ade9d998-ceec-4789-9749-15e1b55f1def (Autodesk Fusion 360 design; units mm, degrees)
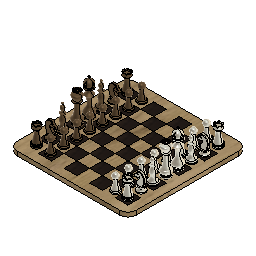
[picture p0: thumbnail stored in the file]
sketch "Sketch1" plane through (0, 0, 0) normal (0, 0, 1) x axis (1, 0, 0)
  line L1 (280, 0) -> (0, 0)
  line L2 (280, 280) -> (280, 0)
  line L3 (0, 280) -> (280, 280)
  line L4 (0, 0) -> (0, 280)
  point P1 (0, 0)
  point P2 (0, 0)
  point P3 (280, 0)
  point P5 (0, 280)
  horizontal L1
  vertical L2
  horizontal L3
  vertical L4
  coincident P1 P2
  dimension "d1" distance P2 P3 = 280
  dimension "d2" distance P2 P5 = 280
extrude "Extrude1" new body sketch "Sketch1" along normal blind 10
sketch "Sketch2" plane through (0, 0, 10) normal (0, 0, 1) x axis (-1, 0, 0)
  line L1 (0, 0) -> (0, -280)
  line L2 (-280, 0) -> (0, 0)
  line L3 (-280, -280) -> (-280, 0)
  line L4 (0, -280) -> (-280, -280)
  line L5 (-50, -260) -> (-20, -260)
  line L6 (-50, -230) -> (-50, -260)
  line L7 (-20, -230) -> (-50, -230)
  line L8 (-20, -260) -> (-20, -230)
  point P6 (-20, -260)
  point P7 (-50, -260)
  point P9 (-20, -230)
  point P2 (0, -280)
  horizontal L5
  vertical L6
  horizontal L7
  vertical L8
  dimension "d5" distance P6 P7 = 30
  dimension "d6" distance P6 P9 = 30
  dimension "d7" distance P2 P6 = 20
  dimension "d8" distance L4 L5 = 20
extrude "Extrude2" cut sketch "Sketch2" profile of L5 L6 L7 L8 against normal blind 10
rectangular_pattern "R-Pattern1" uSpaceDistance -60 vSpaceDistance -60
sketch "Sketch3" plane through (0, 0, 10) normal (0, 0, 1) x axis (-1, 0, 0)
  line L1 (-230, -50) -> (-230, -80)
  line L2 (-200, -50) -> (-230, -50)
  line L3 (-200, -80) -> (-200, -50)
  line L4 (-230, -80) -> (-200, -80)
  line L5 (-170, -50) -> (-170, -80)
  line L6 (-140, -50) -> (-170, -50)
  line L7 (-140, -80) -> (-140, -50)
  line L8 (-170, -80) -> (-140, -80)
  line L9 (-110, -50) -> (-110, -80)
  line L10 (-80, -50) -> (-110, -50)
  line L11 (-80, -80) -> (-80, -50)
  line L12 (-110, -80) -> (-80, -80)
  line L13 (-50, -50) -> (-50, -80)
  line L14 (-20, -50) -> (-50, -50)
  line L15 (-20, -80) -> (-20, -50)
  line L16 (-50, -80) -> (-20, -80)
  line L17 (-230, -110) -> (-230, -140)
  line L18 (-200, -110) -> (-230, -110)
  line L19 (-200, -140) -> (-200, -110)
  line L20 (-230, -140) -> (-200, -140)
  line L21 (-170, -110) -> (-170, -140)
  line L22 (-140, -110) -> (-170, -110)
  line L23 (-140, -140) -> (-140, -110)
  line L24 (-170, -140) -> (-140, -140)
  line L25 (-110, -110) -> (-110, -140)
  line L26 (-80, -110) -> (-110, -110)
  line L27 (-80, -140) -> (-80, -110)
  line L28 (-110, -140) -> (-80, -140)
  line L29 (-50, -110) -> (-50, -140)
  line L30 (-20, -110) -> (-50, -110)
  line L31 (-20, -140) -> (-20, -110)
  line L32 (-50, -140) -> (-20, -140)
  line L33 (-230, -170) -> (-230, -200)
  line L34 (-200, -170) -> (-230, -170)
  line L35 (-200, -200) -> (-200, -170)
  line L36 (-230, -200) -> (-200, -200)
  line L37 (-170, -170) -> (-170, -200)
  line L38 (-140, -170) -> (-170, -170)
  line L39 (-140, -200) -> (-140, -170)
  line L40 (-170, -200) -> (-140, -200)
  line L41 (-110, -170) -> (-110, -200)
  line L42 (-80, -170) -> (-110, -170)
  line L43 (-80, -200) -> (-80, -170)
  line L44 (-110, -200) -> (-80, -200)
  line L45 (-50, -170) -> (-50, -200)
  line L46 (-20, -170) -> (-50, -170)
  line L47 (-20, -200) -> (-20, -170)
  line L48 (-50, -200) -> (-20, -200)
  line L49 (-230, -230) -> (-230, -260)
  line L50 (-200, -230) -> (-230, -230)
  line L51 (-200, -260) -> (-200, -230)
  line L52 (-230, -260) -> (-200, -260)
  line L53 (-170, -230) -> (-170, -260)
  line L54 (-140, -230) -> (-170, -230)
  line L55 (-140, -260) -> (-140, -230)
  line L56 (-170, -260) -> (-140, -260)
  line L57 (-110, -230) -> (-110, -260)
  line L58 (-80, -230) -> (-110, -230)
  line L59 (-80, -260) -> (-80, -230)
  line L60 (-110, -260) -> (-80, -260)
  line L61 (-50, -230) -> (-50, -260)
  line L62 (-20, -230) -> (-50, -230)
  line L63 (-20, -260) -> (-20, -230)
  line L64 (-50, -260) -> (-20, -260)
  line L65 (0, 0) -> (0, -280)
  line L66 (-280, 0) -> (0, 0)
  line L67 (-280, -280) -> (-280, 0)
  line L68 (0, -280) -> (-280, -280)
  line L69 (-80, -20) -> (-50, -20)
  line L70 (-80, -50) -> (-80, -20)
  line L71 (-50, -50) -> (-80, -50)
  line L72 (-50, -20) -> (-50, -50)
  point P70 (-50, -20)
  point P71 (-80, -20)
  point P73 (-50, -50)
  horizontal L69
  vertical L70
  horizontal L71
  vertical L72
  dimension "d15" distance P70 P71 = 30
  dimension "d16" distance P70 P73 = 30
  dimension "d17" distance L66 L69 = 20
  dimension "d18" distance L65 L72 = 50
extrude "Extrude3" cut sketch "Sketch3" profile of L69 L70 L71 L72 against normal blind 10
rectangular_pattern "R-Pattern2" uSpaceDistance -60 vSpaceDistance -60
sketch "Sketch1" plane through (0, 0, 10) normal (0, 0, 1) x axis (-1, 0, 0)
  line L1 (-260, -230) -> (-230, -230)
  line L2 (-260, -200) -> (-260, -230)
  line L3 (-230, -200) -> (-260, -200)
  line L4 (-230, -170) -> (-230, -200)
  line L5 (-260, -170) -> (-230, -170)
  line L6 (-260, -140) -> (-260, -170)
  line L7 (-230, -140) -> (-260, -140)
  line L8 (-230, -110) -> (-230, -140)
  line L9 (-260, -110) -> (-230, -110)
  line L10 (-260, -80) -> (-260, -110)
  line L11 (-230, -80) -> (-260, -80)
  line L12 (-230, -50) -> (-230, -80)
  line L13 (-260, -50) -> (-230, -50)
  line L14 (-260, -20) -> (-260, -50)
  line L15 (-230, -20) -> (-260, -20)
  line L16 (-230, -50) -> (-230, -20)
  line L17 (-200, -50) -> (-230, -50)
  line L18 (-200, -20) -> (-200, -50)
  line L19 (-170, -20) -> (-200, -20)
  line L20 (-170, -50) -> (-170, -20)
  line L21 (-140, -50) -> (-170, -50)
  line L22 (-140, -20) -> (-140, -50)
  line L23 (-110, -20) -> (-140, -20)
  line L24 (-110, -50) -> (-110, -20)
  line L25 (-80, -50) -> (-110, -50)
  line L26 (-80, -20) -> (-80, -50)
  line L27 (-50, -20) -> (-80, -20)
  line L28 (-50, -50) -> (-50, -20)
  line L29 (-20, -50) -> (-50, -50)
  line L30 (-20, -80) -> (-20, -50)
  line L31 (-50, -80) -> (-20, -80)
  line L32 (-50, -110) -> (-50, -80)
  line L33 (-20, -110) -> (-50, -110)
  line L34 (-20, -140) -> (-20, -110)
  line L35 (-50, -140) -> (-20, -140)
  line L36 (-50, -170) -> (-50, -140)
  line L37 (-20, -170) -> (-50, -170)
  line L38 (-20, -200) -> (-20, -170)
  line L39 (-50, -200) -> (-20, -200)
  line L40 (-50, -230) -> (-50, -200)
  line L41 (-20, -230) -> (-50, -230)
  line L42 (-20, -260) -> (-20, -230)
  line L43 (-50, -260) -> (-20, -260)
  line L44 (-50, -230) -> (-50, -260)
  line L45 (-80, -230) -> (-50, -230)
  line L46 (-80, -260) -> (-80, -230)
  line L47 (-110, -260) -> (-80, -260)
  line L48 (-110, -230) -> (-110, -260)
  line L49 (-140, -230) -> (-110, -230)
  line L50 (-140, -260) -> (-140, -230)
  line L51 (-170, -260) -> (-140, -260)
  line L52 (-170, -230) -> (-170, -260)
  line L53 (-200, -230) -> (-170, -230)
  line L54 (-200, -260) -> (-200, -230)
  line L55 (-230, -260) -> (-200, -260)
  line L56 (-230, -230) -> (-230, -260)
  line L57 (0, 0) -> (0, -280)
  line L58 (-280, 0) -> (0, 0)
  line L59 (-280, -280) -> (-280, 0)
  line L60 (0, -280) -> (-280, -280)
  line L61 (-80, -50) -> (-50, -50)
  line L62 (-80, -20) -> (-80, -50)
  line L63 (-50, -20) -> (-80, -20)
  line L64 (-50, -50) -> (-50, -20)
  point P60 (-50, -50)
  point P61 (-80, -50)
  point P63 (-50, -20)
  point P1 (0, 0)
  horizontal L61
  vertical L62
  horizontal L63
  vertical L64
  dimension "d25" distance P60 P61 = 30
  dimension "d26" distance P60 P63 = 30
  dimension "d27" distance P1 L64 = 50
  dimension "d28" distance L58 L63 = 20
extrude "Extrude1" new body sketch "Sketch1" profile of L26 L27 L28 L61 L62 L63 L64 against normal blind 10
rectangular_pattern "R-Pattern1" uSpaceDistance 60 vSpaceDistance 60
sketch "Sketch2" plane through (0, 0, 10) normal (0, 0, 1) x axis (-1, 0, 0)
  line L1 (-260, -230) -> (-230, -230)
  line L2 (-260, -200) -> (-260, -230)
  line L3 (-230, -200) -> (-260, -200)
  line L4 (-230, -170) -> (-230, -200)
  line L5 (-260, -170) -> (-230, -170)
  line L6 (-260, -140) -> (-260, -170)
  line L7 (-230, -140) -> (-260, -140)
  line L8 (-230, -110) -> (-230, -140)
  line L9 (-260, -110) -> (-230, -110)
  line L10 (-260, -80) -> (-260, -110)
  line L11 (-230, -80) -> (-260, -80)
  line L12 (-230, -50) -> (-230, -80)
  line L13 (-260, -50) -> (-230, -50)
  line L14 (-260, -20) -> (-260, -50)
  line L15 (-230, -20) -> (-260, -20)
  line L16 (-230, -50) -> (-230, -20)
  line L17 (-200, -50) -> (-230, -50)
  line L18 (-200, -20) -> (-200, -50)
  line L19 (-170, -20) -> (-200, -20)
  line L20 (-170, -50) -> (-170, -20)
  line L21 (-140, -50) -> (-170, -50)
  line L22 (-140, -20) -> (-140, -50)
  line L23 (-110, -20) -> (-140, -20)
  line L24 (-110, -50) -> (-110, -20)
  line L25 (-80, -50) -> (-110, -50)
  line L26 (-80, -20) -> (-80, -50)
  line L27 (-50, -20) -> (-80, -20)
  line L28 (-50, -50) -> (-50, -20)
  line L29 (-20, -50) -> (-50, -50)
  line L30 (-20, -80) -> (-20, -50)
  line L31 (-50, -80) -> (-20, -80)
  line L32 (-50, -110) -> (-50, -80)
  line L33 (-20, -110) -> (-50, -110)
  line L34 (-20, -140) -> (-20, -110)
  line L35 (-50, -140) -> (-20, -140)
  line L36 (-50, -170) -> (-50, -140)
  line L37 (-20, -170) -> (-50, -170)
  line L38 (-20, -200) -> (-20, -170)
  line L39 (-50, -200) -> (-20, -200)
  line L40 (-50, -230) -> (-50, -200)
  line L41 (-20, -230) -> (-50, -230)
  line L42 (-20, -260) -> (-20, -230)
  line L43 (-50, -260) -> (-20, -260)
  line L44 (-50, -230) -> (-50, -260)
  line L45 (-80, -230) -> (-50, -230)
  line L46 (-80, -260) -> (-80, -230)
  line L47 (-110, -260) -> (-80, -260)
  line L48 (-110, -230) -> (-110, -260)
  line L49 (-140, -230) -> (-110, -230)
  line L50 (-140, -260) -> (-140, -230)
  line L51 (-170, -260) -> (-140, -260)
  line L52 (-170, -230) -> (-170, -260)
  line L53 (-200, -230) -> (-170, -230)
  line L54 (-200, -260) -> (-200, -230)
  line L55 (-230, -260) -> (-200, -260)
  line L56 (-230, -230) -> (-230, -260)
  line L57 (0, 0) -> (0, -280)
  line L58 (-280, 0) -> (0, 0)
  line L59 (-280, -280) -> (-280, 0)
  line L60 (0, -280) -> (-280, -280)
  line L61 (-50, -80) -> (-20, -80)
  line L62 (-50, -50) -> (-50, -80)
  line L63 (-20, -50) -> (-50, -50)
  line L64 (-20, -80) -> (-20, -50)
  point P29 (-50, -50)
  point P62 (-50, -50)
  point P31 (-20, -80)
  point P60 (-20, -80)
  horizontal L61
  vertical L62
  horizontal L63
  vertical L64
  coincident P29 P62
  coincident P31 P60
extrude "Extrude2" new body sketch "Sketch2" profile of L29 L30 L31 L61 L62 L63 L64 against normal blind 10
rectangular_pattern "R-Pattern2" uSpaceDistance 60 vSpaceDistance 60
fillet "Fillet1" radius 20
component_insert "Component Insert2"
rectangular_pattern "㠁" uSpaceDistance 30.503 vSpaceDistance -151.999
component_insert "Component Insert3"
rectangular_pattern "锁" uSpaceDistance 208.567 vSpaceDistance 0
component_insert "Component Insert4"
rectangular_pattern "ጁ" uSpaceDistance 208.34 vSpaceDistance 0
component_insert "Component Insert5"
rectangular_pattern "蠁" uSpaceDistance 213.872 vSpaceDistance 212.188
component_insert "Component Insert6"
rectangular_pattern "搁" uSpaceDistance 148.839 vSpaceDistance 0
component_insert "Component Insert7"
rectangular_pattern "" uSpaceDistance 211.83 vSpaceDistance 90.565
component_insert "Component Insert8"
rectangular_pattern "㌁" uSpaceDistance 149.468 vSpaceDistance 0
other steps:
create_component "CreateComponent1"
